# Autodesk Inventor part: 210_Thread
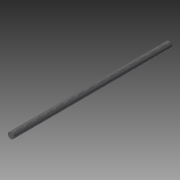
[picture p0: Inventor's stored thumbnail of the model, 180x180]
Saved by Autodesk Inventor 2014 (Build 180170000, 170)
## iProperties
Created: 2013-12
Part Number: 210_Thread
Material: Stainless Steel
Document SubType Name: Modeling
Designer: Bram
Density: 8.08 g/cm^3
Appearance: Semi-Polished
Author: Bram
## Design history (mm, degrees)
sketch "Sketch1"
  geometry: C1 r 4 at (0, 0); 1 further point
  constraints: 1 centre point, 1 coincident
  dimensions: "d0" = 8 diameter of C1
extrude "Extrusion1" new body sketch "Sketch1" distance "d1" = 210; taper "d2" = 0 deg
thread "Thread1" dims "d3" = 10, "d4" = 0
body "Solid1"
